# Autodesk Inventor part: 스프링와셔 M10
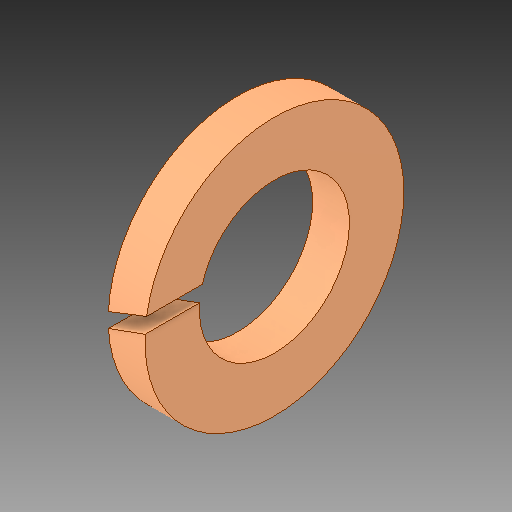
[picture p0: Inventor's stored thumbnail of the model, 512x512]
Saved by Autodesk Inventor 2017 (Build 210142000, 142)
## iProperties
Created: 2024-09
Part Number: 스프링와셔 M10
Material: 일반
Description: 스프링 잠금 와셔
Document SubType Name: Modeling
Designer: MRC
Density: 1 g/cm^3
Appearance: 기본값
Author: jhkim
Sending System: Autodesk Inventor 2025
Preprocessor: ST-DEVELOPER v20
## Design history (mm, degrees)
feature "Solid1"
node "솔리드1"
